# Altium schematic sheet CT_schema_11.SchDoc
size 209 x 185 mm
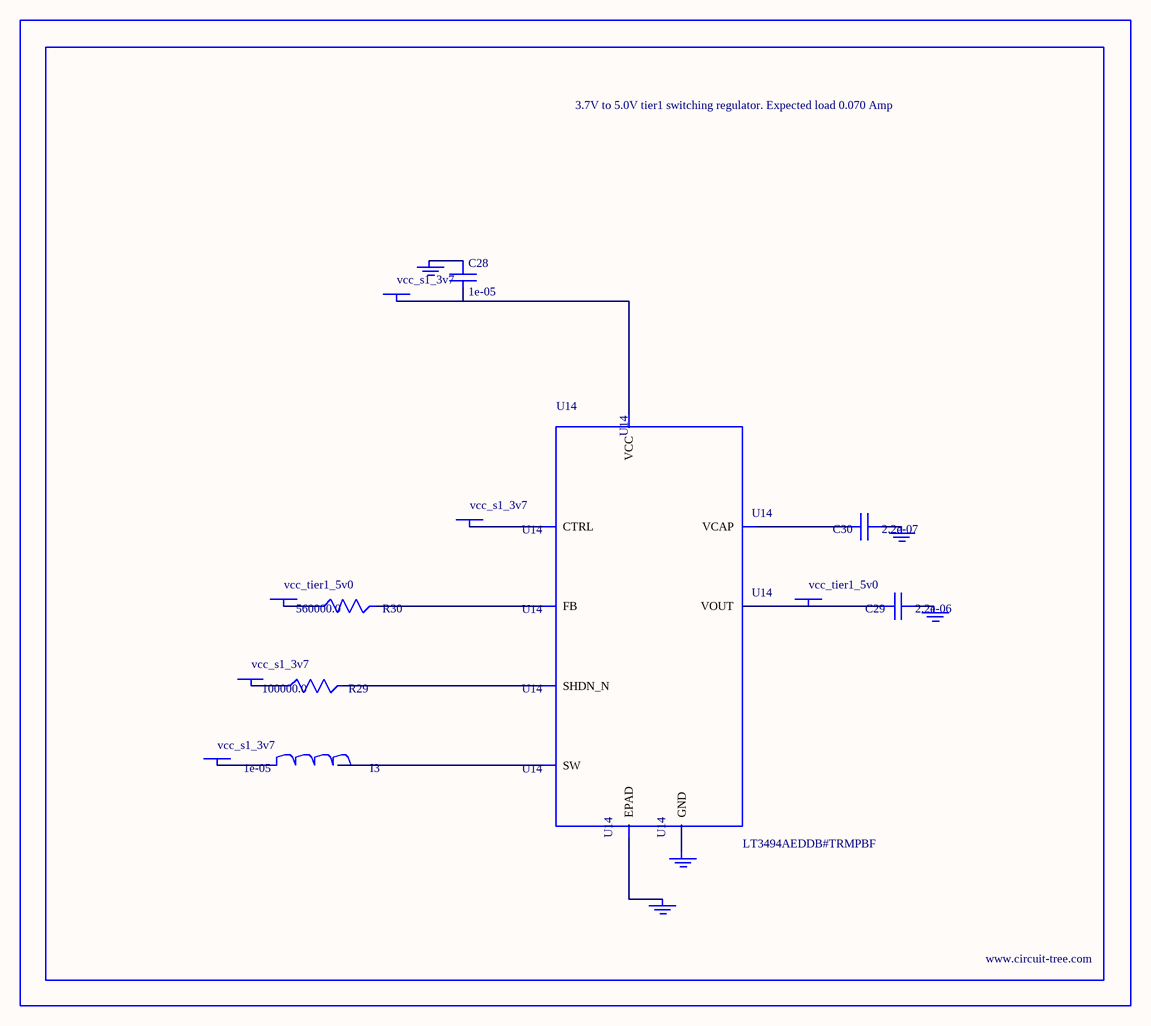
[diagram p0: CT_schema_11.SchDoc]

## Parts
BORDER10  (no value)
C28  1e-05  [C1210]
C29  2.2e-06  [C0603]
C30  2.2e-07  [C0603]
GND_INSTANCE_10_0  (no value)
GND_INSTANCE_10_1  (no value)
GND_INSTANCE_10_2  (no value)
GND_INSTANCE_10_3  (no value)
GND_INSTANCE_10_4  (no value)
I3  1e-05  [L1210]
POWER_INSTANCE_10_0  vcc_s1_3v7
POWER_INSTANCE_10_1  vcc_s1_3v7
POWER_INSTANCE_10_2  vcc_s1_3v7
POWER_INSTANCE_10_3  vcc_s1_3v7
POWER_INSTANCE_10_4  vcc_tier1_5v0
POWER_INSTANCE_10_5  vcc_tier1_5v0
R29  100000.0  [R0603]
R30  560000.0  [R0603]
U14  LT3494AEDDB#TRMPBF  [DFN-8_DDB]

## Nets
NetC28_1: C28.1 GND_INSTANCE_10_0.0(GND)
NetC28_2: C28.2 POWER_INSTANCE_10_1.0(PWR) U14.3(VCC)
NetC29_1: C29.1 GND_INSTANCE_10_1.0(GND)
NetC29_2: C29.2 POWER_INSTANCE_10_5.0(PWR) U14.7(VOUT)
NetC30_1: C30.1 GND_INSTANCE_10_2.0(GND)
NetC30_2: C30.2 U14.8(VCAP)
NetGND_INSTANCE_10_3_0: GND_INSTANCE_10_3.0(GND) U14.9(EPAD)
NetGND_INSTANCE_10_4_0: GND_INSTANCE_10_4.0(GND) U14.2(GND)
NetI3_1: I3.1 POWER_INSTANCE_10_0.0(PWR)
NetI3_2: I3.2 U14.1(SW)
NetPOWER_INSTANCE_10_2_0: POWER_INSTANCE_10_2.0(PWR) U14.4(CTRL)
NetPOWER_INSTANCE_10_3_0: POWER_INSTANCE_10_3.0(PWR) R29.1
NetPOWER_INSTANCE_10_4_0: POWER_INSTANCE_10_4.0(PWR) R30.1
NetR29_2: R29.2 U14.5(SHDN_N)
NetR30_2: R30.2 U14.6(FB)

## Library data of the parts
BORDER10 = BORDER_PAGE10
C28 = C1210C106K5PACTU
C29 = GRM188R61H225KE1115D
C30 = C0603C224K3RAC
GND_INSTANCE_10_0-GND_INSTANCE_10_4 = GND
I3 = CBC3225T100MR
POWER_INSTANCE_10_0-POWER_INSTANCE_10_5 = PWR
R29 = RC0603JR-07100KL
R30 = RC0603JR-07560KL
